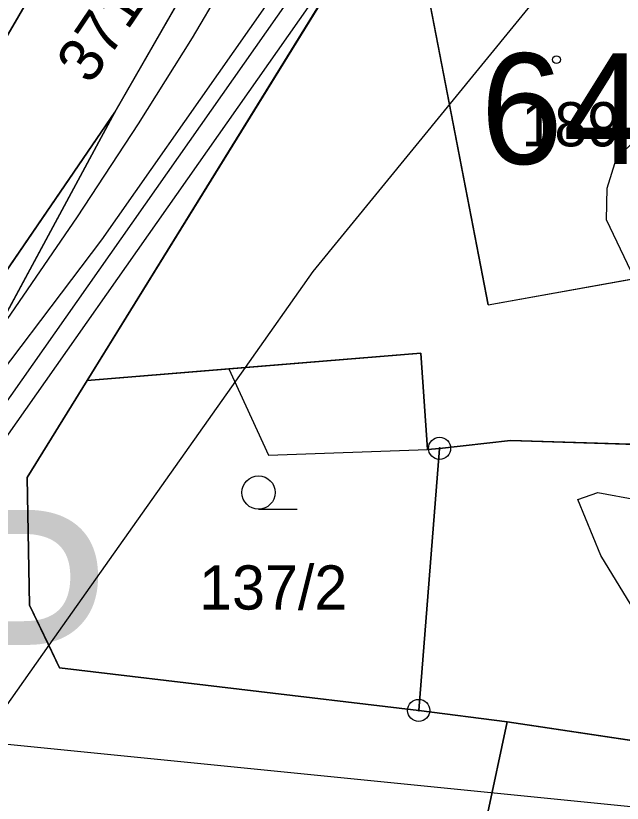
# Model space of a CAD drawing. Extents: x -706130 to -698555, y -971544 to -967260.
# Drawn here: x -704302.51 to -704275.12, y -970113.78 to -970078.18 of the extents above; entities that cross this region are included whole.
import ezdxf

# ---------------------------------------------------------------- set-up
doc = ezdxf.new("R2010")
doc.units = 0
for name, color, linetype in [('_Doplněk budov pro zastavěnost', 7, 'Continuous'), ('BPEJ hranice S', 7, 'Continuous'), ('BPEJ I-II trida ochrany S', 7, 'Continuous'), ('Docházková izochrona - BUS S', 7, 'Continuous'), ('Docházková izochrona - VLAK N', 7, 'Continuous'), ('Hranice intravilán', 7, 'Continuous'), ('Kanalizace_stoka bez rozlišení N', 7, 'Continuous'), ('KN_Budovy', 7, 'Continuous'), ('KN_Budovy_cisla_domovni', 7, 'Continuous'), ('KN_Hranice_parcel', 7, 'Continuous'), ('KN_Hranice_parcel_vnitrni_kresba', 7, 'Continuous'), ('KN_Parcelni cisla', 7, 'Continuous'), ('KN_Polygon parcely', 7, 'Continuous'), ('KN_POZEMKY_11_VODNI_PLOCHA', 7, 'Continuous'), ('KN_POZEMKY_13_ZASTAVENA PLOCHA', 7, 'Continuous'), ('KN_POZEMKY_14_OSTATNI PLOCHA', 7, 'Continuous'), ('KN_POZEMKY_5_ZAHRADA', 7, 'Continuous'), ('KN_POZEMKY_7_TTP', 7, 'Continuous'), ('KN_VYUZITI_07_vodni plocha_tok prirozeny', 7, 'Continuous'), ('KN_VYUZITI_17_ostatni plocha_ostatni komunikace', 7, 'Continuous'), ('KN_VYUZITI_26_ostatni plocha_jina plocha', 7, 'Continuous'), ('KN_Značky bodu BP', 7, 'Continuous'), ('KN_Značky budov', 7, 'Continuous'), ('KN_Značky kultur', 7, 'Continuous'), ('Nemovité kulturní památky S', 7, 'Continuous'), ('Plochy smíšené obytné venkovské S', 7, 'Continuous'), ('Plochy verejnych prostranstvi - komunikace ostatni S', 7, 'Continuous'), ('Plochy vodní a vodnich toku S', 7, 'Continuous'), ('Plochy zeleně sídelní ostatní S', 7, 'Continuous'), ('Plynovody STL S', 7, 'Continuous'), ('Regulační bloky v krajině S', 7, 'Continuous'), ('Regulační bloky v krajině S  TIS', 7, 'Continuous'), ('Regulační bloky zastavěné S', 7, 'Continuous'), ('Regulační kódy zastavěné S', 7, 'Continuous'), ('Vodovodní řady - rozváděcí S', 7, 'Continuous'), ('Záplavové území stanovene S', 7, 'Continuous'), ('Záplavového území_aktivní zóna S', 7, 'Continuous')]:
    doc.layers.add(name, color=color, linetype=linetype)

msp = doc.modelspace()

# ---------------------------------------------------------------- linework, layer by layer
at = {"layer": '_Doplněk budov pro zastavěnost'}
for p, q in [((-704292.892, -970094.149), (-704291.097, -970098.056)), ((-704291.097, -970098.056), (-704283.91, -970097.8))]:
    msp.add_line(p, q, dxfattribs=at)
msp.add_lwpolyline([(-704283.91, -970097.8), (-704284.21, -970093.44), (-704292.892, -970094.149)], dxfattribs=at)
at = {"layer": 'BPEJ hranice S'}
msp.add_lwpolyline([(-704231.944, -970030.101), (-704236.746, -970033.05), (-704250.684, -970046.683), (-704262.658, -970058.435), (-704267.099, -970062.795), (-704272.175, -970069.016), (-704289.09, -970089.752), (-704292.154, -970094.088), (-704301.02, -970106.64), (-704305.506, -970112.991), (-704308.371, -970116.142), (-704315.893, -970124.421), (-704317.877, -970126.604), (-704320.992, -970130.033), (-704322.312, -970131.353), (-704329.974, -970139.019)], dxfattribs=at)
at = {"layer": 'BPEJ I-II trida ochrany S'}
for p, q in [((-704303.4, -970079.95), (-704300.98, -970075.77)), ((-704284.21, -970093.44), (-704292.154, -970094.088)), ((-704283.91, -970097.8), (-704284.21, -970093.44)), ((-704292.154, -970094.088), (-704299.28, -970094.67)), ((-704299.28, -970094.67), (-704301.99, -970099.06)), ((-704280.16, -970097.38), (-704283.37, -970097.74)), ((-704270.7, -970097.69), (-704280.16, -970097.38)), ((-704283.37, -970097.74), (-704283.91, -970097.8)), ((-704301.99, -970099.06), (-704301.89, -970104.83)), ((-704301.89, -970104.83), (-704301.02, -970106.64)), ((-704301.02, -970106.64), (-704300.53, -970107.66)), ((-704300.53, -970107.66), (-704284.31, -970109.59)), ((-704284.31, -970109.59), (-704280.31, -970110.11)), ((-704280.31, -970110.11), (-704258.53, -970113.37))]:
    msp.add_line(p, q, dxfattribs=at)
at = {"layer": 'Docházková izochrona - BUS S'}
msp.add_arc((-704361.829, -969946.93), 400, 155.51821, 17.33949, dxfattribs=at)
at = {"layer": 'Docházková izochrona - VLAK N'}
msp.add_circle((-704165.451, -969778.767), 800, dxfattribs=at)
at = {"layer": 'Hranice intravilán'}
msp.add_lwpolyline([(-704226.27, -970097.78), (-704237.91, -970097.99), (-704238.92, -970098), (-704251.82, -970098.14), (-704255.6, -970098.18), (-704254.66, -970106.84), (-704258.53, -970113.37), (-704280.31, -970110.11), (-704281.24, -970114.41), (-704249.26, -970126.19), (-704248.64, -970123.84), (-704243.56, -970125.14), (-704244.29, -970127.99), (-704247.64, -970141.18), (-704257.15, -970138.75), (-704260.52, -970150.22), (-704222.31, -970155.39)], dxfattribs=at)
at = {"layer": 'Kanalizace_stoka bez rozlišení N'}
msp.add_line((-704312.052, -970110.204), (-704263.944, -970115.005), dxfattribs=at)
msp.add_lwpolyline([(-704312.052, -970110.204), (-704285.646, -970072.578), (-704255.613, -970061.083)], dxfattribs=at)
at = {"layer": 'KN_Budovy'}
msp.add_lwpolyline([(-704284.59, -970073.54), (-704281.18, -970091.26), (-704268.79, -970089.03), (-704266.68, -970088.65), (-704267.76, -970083.06), (-704271.88, -970083.8), (-704273.63, -970074.7), (-704274.9, -970073.85), (-704277.83, -970074.38), (-704278.22, -970072.33)], close=True, dxfattribs=at)
at = {"layer": 'KN_Hranice_parcel'}
for p, q in [((-704298.03, -970082.54), (-704288.02, -970065.08)), ((-704284.31, -970109.59), (-704283.37, -970097.74)), ((-704280.31, -970110.11), (-704284.31, -970109.59)), ((-704281.24, -970114.41), (-704280.31, -970110.11))]:
    msp.add_line(p, q, dxfattribs=at)
for points in [[(-704284.59, -970073.54), (-704288.09, -970076.54), (-704299.28, -970094.67)], [(-704300.98, -970075.77), (-704303.4, -970079.95), (-704311.02, -970091.22)], [(-704318.05, -970107.85), (-704306.33, -970094.67), (-704298.03, -970082.54)], [(-704298.03, -970082.54), (-704305.17, -970095.76), (-704318.05, -970107.85)], [(-704299.28, -970094.67), (-704284.21, -970093.44), (-704283.91, -970097.8), (-704283.37, -970097.74)], [(-704299.28, -970094.67), (-704301.99, -970099.06), (-704301.89, -970104.83), (-704300.53, -970107.66), (-704284.31, -970109.59)], [(-704283.37, -970097.74), (-704280.16, -970097.38), (-704270.7, -970097.69)], [(-704254.66, -970106.84), (-704258.53, -970113.37), (-704280.31, -970110.11)]]:
    msp.add_lwpolyline(points, dxfattribs=at)
at = {"layer": 'KN_Hranice_parcel_vnitrni_kresba'}
for q in [(-704284.59, -970073.54), (-704268.79, -970089.03)]:
    msp.add_line((-704281.18, -970091.26), q, dxfattribs=at)
at = {"layer": 'KN_Polygon parcely'}
for points in [[(-704304.13, -970029.78), (-704293.8, -970048.28), (-704290.66, -970057.13), (-704291.17, -970061.73), (-704295.56, -970068.02), (-704300.98, -970075.77), (-704303.4, -970079.95), (-704311.02, -970091.22), (-704320.51, -970101.33), (-704324.43, -970099.46), (-704323.51, -970113.12), (-704320.89, -970110.65), (-704318.08, -970109.89), (-704318.05, -970107.85), (-704306.33, -970094.67), (-704298.03, -970082.54), (-704288.02, -970065.08), (-704286.95, -970063.22), (-704286.42, -970056.27), (-704289.72, -970046.84), (-704299.25, -970030.39)], [(-704281.24, -970114.41), (-704280.31, -970110.11), (-704284.31, -970109.59), (-704300.53, -970107.66), (-704301.89, -970104.83), (-704301.99, -970099.06), (-704299.28, -970094.67), (-704288.09, -970076.54), (-704284.59, -970073.54), (-704287.5, -970066.36), (-704288.02, -970065.08), (-704298.03, -970082.54), (-704305.17, -970095.76), (-704318.05, -970107.85), (-704318.08, -970109.89), (-704320.89, -970110.65), (-704323.51, -970113.12), (-704321.91, -970137.46)]]:
    msp.add_lwpolyline(points, dxfattribs=at)
for points in [[(-704311.02, -970091.22), (-704303.4, -970079.95), (-704300.98, -970075.77), (-704295.56, -970068.02), (-704300.3, -970068.99), (-704302.9, -970069.53), (-704301.86, -970073.82)], [(-704266.86, -970079.24), (-704263.44, -970074.15), (-704271.47, -970068.76), (-704284.59, -970073.54), (-704288.09, -970076.54), (-704299.28, -970094.67), (-704284.21, -970093.44), (-704283.91, -970097.8), (-704283.37, -970097.74), (-704280.16, -970097.38), (-704270.7, -970097.69), (-704266.68, -970088.65), (-704267.76, -970083.06), (-704271.88, -970083.8), (-704273.63, -970074.7)], [(-704318.05, -970107.85), (-704305.17, -970095.76), (-704298.03, -970082.54), (-704306.33, -970094.67)], [(-704300.53, -970107.66), (-704284.31, -970109.59), (-704283.37, -970097.74), (-704283.91, -970097.8), (-704284.21, -970093.44), (-704299.28, -970094.67), (-704301.99, -970099.06), (-704301.89, -970104.83)], [(-704283.37, -970097.74), (-704284.31, -970109.59), (-704280.31, -970110.11), (-704258.53, -970113.37), (-704254.66, -970106.84), (-704255.6, -970098.18), (-704270.7, -970097.69), (-704280.16, -970097.38)], [(-704211.05, -970124.6), (-704252.61, -970117.28), (-704252.65, -970109.96), (-704254.33, -970109.82), (-704254.66, -970106.84), (-704258.53, -970113.37), (-704280.31, -970110.11), (-704281.24, -970114.41), (-704249.26, -970126.19), (-704248.64, -970123.84), (-704243.56, -970125.14), (-704244.29, -970127.99), (-704242.29, -970128.72), (-704214.21, -970130.67)]]:
    msp.add_lwpolyline(points, close=True, dxfattribs=at)
at = {"layer": 'KN_POZEMKY_11_VODNI_PLOCHA'}
for p, q in [((-704288.02, -970065.08), (-704298.03, -970082.54)), ((-704303.4, -970079.95), (-704300.98, -970075.77)), ((-704298.03, -970082.54), (-704306.33, -970094.67))]:
    msp.add_line(p, q, dxfattribs=at)
at = {"layer": 'KN_POZEMKY_13_ZASTAVENA PLOCHA'}
for p, q in [((-704299.28, -970094.67), (-704288.09, -970076.54)), ((-704284.21, -970093.44), (-704299.28, -970094.67)), ((-704283.91, -970097.8), (-704284.21, -970093.44)), ((-704280.16, -970097.38), (-704283.37, -970097.74)), ((-704270.7, -970097.69), (-704280.16, -970097.38)), ((-704283.37, -970097.74), (-704283.91, -970097.8))]:
    msp.add_line(p, q, dxfattribs=at)
at = {"layer": 'KN_POZEMKY_14_OSTATNI PLOCHA'}
for p, q in [((-704298.03, -970082.54), (-704288.02, -970065.08)), ((-704288.09, -970076.54), (-704299.28, -970094.67)), ((-704306.33, -970094.67), (-704298.03, -970082.54)), ((-704305.17, -970095.76), (-704298.03, -970082.54)), ((-704298.03, -970082.54), (-704305.17, -970095.76)), ((-704299.28, -970094.67), (-704301.99, -970099.06)), ((-704301.99, -970099.06), (-704301.89, -970104.83)), ((-704301.89, -970104.83), (-704300.53, -970107.66)), ((-704300.53, -970107.66), (-704284.31, -970109.59)), ((-704284.31, -970109.59), (-704280.31, -970110.11)), ((-704280.31, -970110.11), (-704281.24, -970114.41)), ((-704281.24, -970114.41), (-704280.31, -970110.11)), ((-704280.31, -970110.11), (-704258.53, -970113.37))]:
    msp.add_line(p, q, dxfattribs=at)
at = {"layer": 'KN_POZEMKY_5_ZAHRADA'}
for p, q in [((-704299.28, -970094.67), (-704284.21, -970093.44)), ((-704284.21, -970093.44), (-704283.91, -970097.8)), ((-704301.99, -970099.06), (-704299.28, -970094.67)), ((-704283.37, -970097.74), (-704280.16, -970097.38)), ((-704280.16, -970097.38), (-704270.7, -970097.69)), ((-704283.37, -970097.74), (-704284.31, -970109.59)), ((-704284.31, -970109.59), (-704283.37, -970097.74)), ((-704283.91, -970097.8), (-704283.37, -970097.74)), ((-704301.89, -970104.83), (-704301.99, -970099.06)), ((-704300.53, -970107.66), (-704301.89, -970104.83)), ((-704284.31, -970109.59), (-704300.53, -970107.66)), ((-704280.31, -970110.11), (-704284.31, -970109.59)), ((-704258.53, -970113.37), (-704280.31, -970110.11))]:
    msp.add_line(p, q, dxfattribs=at)
at = {"layer": 'KN_POZEMKY_7_TTP'}
msp.add_line((-704300.98, -970075.77), (-704303.4, -970079.95), dxfattribs=at)
at = {"layer": 'KN_VYUZITI_07_vodni plocha_tok prirozeny'}
for p, q in [((-704288.02, -970065.08), (-704298.03, -970082.54)), ((-704303.4, -970079.95), (-704300.98, -970075.77)), ((-704298.03, -970082.54), (-704306.33, -970094.67))]:
    msp.add_line(p, q, dxfattribs=at)
at = {"layer": 'KN_VYUZITI_17_ostatni plocha_ostatni komunikace'}
for p, q in [((-704298.03, -970082.54), (-704288.02, -970065.08)), ((-704288.09, -970076.54), (-704299.28, -970094.67)), ((-704305.17, -970095.76), (-704298.03, -970082.54)), ((-704299.28, -970094.67), (-704301.99, -970099.06)), ((-704301.99, -970099.06), (-704301.89, -970104.83)), ((-704301.89, -970104.83), (-704300.53, -970107.66)), ((-704300.53, -970107.66), (-704284.31, -970109.59)), ((-704284.31, -970109.59), (-704280.31, -970110.11)), ((-704280.31, -970110.11), (-704281.24, -970114.41)), ((-704281.24, -970114.41), (-704280.31, -970110.11)), ((-704280.31, -970110.11), (-704258.53, -970113.37))]:
    msp.add_line(p, q, dxfattribs=at)
at = {"layer": 'KN_VYUZITI_26_ostatni plocha_jina plocha'}
for p, q in [((-704306.33, -970094.67), (-704298.03, -970082.54)), ((-704298.03, -970082.54), (-704305.17, -970095.76))]:
    msp.add_line(p, q, dxfattribs=at)
at = {"layer": 'KN_Značky bodu BP'}
for centre, radius in [((-704283.37, -970097.74), 0.5), ((-704283.37, -970097.74), 0.0303), ((-704284.31, -970109.59), 0.5), ((-704284.31, -970109.59), 0.0303)]:
    msp.add_circle(centre, radius, dxfattribs=at)
at = {"layer": 'KN_Značky budov'}
msp.add_circle((-704278.087, -970080.169), 0.175, dxfattribs=at)
at = {"layer": 'KN_Značky kultur'}
msp.add_line((-704291.543, -970100.49), (-704289.793, -970100.49), dxfattribs=at)
msp.add_circle((-704291.543, -970099.74), 0.75, dxfattribs=at)
at = {"layer": 'Nemovité kulturní památky S'}
msp.add_lwpolyline([(-704284.59, -970073.54), (-704281.18, -970091.26), (-704268.79, -970089.03), (-704266.68, -970088.65), (-704267.76, -970083.06), (-704271.88, -970083.8), (-704273.63, -970074.7), (-704274.9, -970073.85), (-704277.83, -970074.38), (-704278.22, -970072.33)], close=True, dxfattribs=at)
at = {"layer": 'Plochy smíšené obytné venkovské S'}
for p, q in [((-704288.09, -970076.54), (-704299.28, -970094.67)), ((-704299.28, -970094.67), (-704301.99, -970099.06)), ((-704300.53, -970107.66), (-704284.31, -970109.59)), ((-704284.31, -970109.59), (-704280.31, -970110.11)), ((-704280.31, -970110.11), (-704281.24, -970114.41))]:
    msp.add_line(p, q, dxfattribs=at)
msp.add_lwpolyline([(-704301.99, -970099.06), (-704301.89, -970104.83), (-704300.53, -970107.66)], dxfattribs=at)
at = {"layer": 'Plochy verejnych prostranstvi - komunikace ostatni S'}
for p, q in [((-704288.02, -970065.08), (-704298.03, -970082.54)), ((-704298.03, -970082.54), (-704306.33, -970094.67)), ((-704300.53, -970107.66), (-704301.89, -970104.83)), ((-704284.31, -970109.59), (-704300.53, -970107.66)), ((-704280.31, -970110.11), (-704284.31, -970109.59)), ((-704281.24, -970114.41), (-704280.31, -970110.11))]:
    msp.add_line(p, q, dxfattribs=at)
msp.add_lwpolyline([(-704301.89, -970104.83), (-704301.99, -970099.06), (-704299.28, -970094.67), (-704288.09, -970076.54)], dxfattribs=at)
at = {"layer": 'Plochy vodní a vodnich toku S'}
for p, q in [((-704298.03, -970082.54), (-704288.02, -970065.08)), ((-704300.98, -970075.77), (-704303.4, -970079.95)), ((-704306.33, -970094.67), (-704298.03, -970082.54))]:
    msp.add_line(p, q, dxfattribs=at)
at = {"layer": 'Plochy zeleně sídelní ostatní S'}
msp.add_line((-704303.4, -970079.95), (-704300.98, -970075.77), dxfattribs=at)
at = {"layer": 'Plynovody STL S'}
msp.add_lwpolyline([(-704314.438, -970108.783), (-704313.31, -970107.43), (-704312.508, -970106.41), (-704311.84, -970105.56), (-704310.04, -970103.5), (-704309.02, -970102.03), (-704307.852, -970100.49), (-704305.038, -970096.781), (-704298.62, -970088.32), (-704286.67, -970071.24), (-704265.56, -970062.52), (-704258.896, -970058.945), (-704258.7, -970058.84)], dxfattribs=at)
at = {"layer": 'Regulační bloky v krajině S'}
for p, q in [((-704298.03, -970082.54), (-704288.02, -970065.08)), ((-704300.98, -970075.77), (-704303.4, -970079.95)), ((-704306.33, -970094.67), (-704298.03, -970082.54))]:
    msp.add_line(p, q, dxfattribs=at)
at = {"layer": 'Regulační bloky v krajině S  TIS'}
for p, q in [((-704298.03, -970082.54), (-704288.02, -970065.08)), ((-704300.98, -970075.77), (-704303.4, -970079.95)), ((-704306.33, -970094.67), (-704298.03, -970082.54))]:
    msp.add_line(p, q, dxfattribs=at)
at = {"layer": 'Regulační bloky zastavěné S'}
for p, q in [((-704288.02, -970065.08), (-704298.03, -970082.54)), ((-704303.4, -970079.95), (-704300.98, -970075.77)), ((-704288.09, -970076.54), (-704299.28, -970094.67)), ((-704298.03, -970082.54), (-704306.33, -970094.67)), ((-704299.28, -970094.67), (-704301.99, -970099.06)), ((-704300.53, -970107.66), (-704301.89, -970104.83)), ((-704284.31, -970109.59), (-704300.53, -970107.66)), ((-704300.53, -970107.66), (-704284.31, -970109.59)), ((-704280.31, -970110.11), (-704284.31, -970109.59)), ((-704284.31, -970109.59), (-704280.31, -970110.11)), ((-704281.24, -970114.41), (-704280.31, -970110.11)), ((-704280.31, -970110.11), (-704281.24, -970114.41))]:
    msp.add_line(p, q, dxfattribs=at)
for points in [[(-704301.89, -970104.83), (-704301.99, -970099.06), (-704299.28, -970094.67), (-704288.09, -970076.54)], [(-704301.99, -970099.06), (-704301.89, -970104.83), (-704300.53, -970107.66)]]:
    msp.add_lwpolyline(points, dxfattribs=at)
at = {"layer": 'Vodovodní řady - rozváděcí S'}
msp.add_lwpolyline([(-704256.579, -970059.982), (-704257.004, -970060.15), (-704286.122, -970071.663), (-704321.94, -970122.71)], dxfattribs=at)
at = {"layer": 'Záplavové území stanovene S'}
for points in [[(-704274.391, -970090.403), (-704275.823, -970087.406), (-704275.801, -970085.973), (-704275.378, -970084.628), (-704274.125, -970083.432)], [(-704274.388, -970105.375), (-704276.085, -970102.585), (-704277.125, -970100.048), (-704276.222, -970099.729), (-704274.425, -970100.075)]]:
    msp.add_lwpolyline(points, dxfattribs=at)
at = {"layer": 'Záplavového území_aktivní zóna S'}
msp.add_lwpolyline([(-704327.875, -970116.221), (-704324.792, -970113.458), (-704321.35, -970111.35), (-704320.482, -970111.481), (-704318.344, -970109.58), (-704314.298, -970105.43), (-704312.171, -970103.096), (-704308.799, -970099.257), (-704304.442, -970094.381), (-704303.093, -970092.203), (-704299.722, -970087.275), (-704296.972, -970083.073), (-704294.534, -970079.183), (-704293.25, -970077)], dxfattribs=at)

# ---------------------------------------------------------------- texts
at = {"layer": 'KN_Budovy_cisla_domovni'}
msp.add_text('64', height=5, dxfattribs=at).set_placement((-704281.517, -970084.884))
at = {"layer": 'KN_Parcelni cisla'}
msp.add_text('371/6', height=2, rotation=56, dxfattribs=at).set_placement((-704299.133, -970081.352))
for s, p in [('189', (-704279.67, -970084.09)), ('137/2', (-704294.23, -970105.03))]:
    msp.add_text(s, height=2, dxfattribs=at).set_placement(p)
at = {"layer": 'Regulační kódy zastavěné S'}
msp.add_text('PP', height=10, dxfattribs=at).set_placement((-704315.927, -970110.521))

doc.saveas('drawing.dxf')
